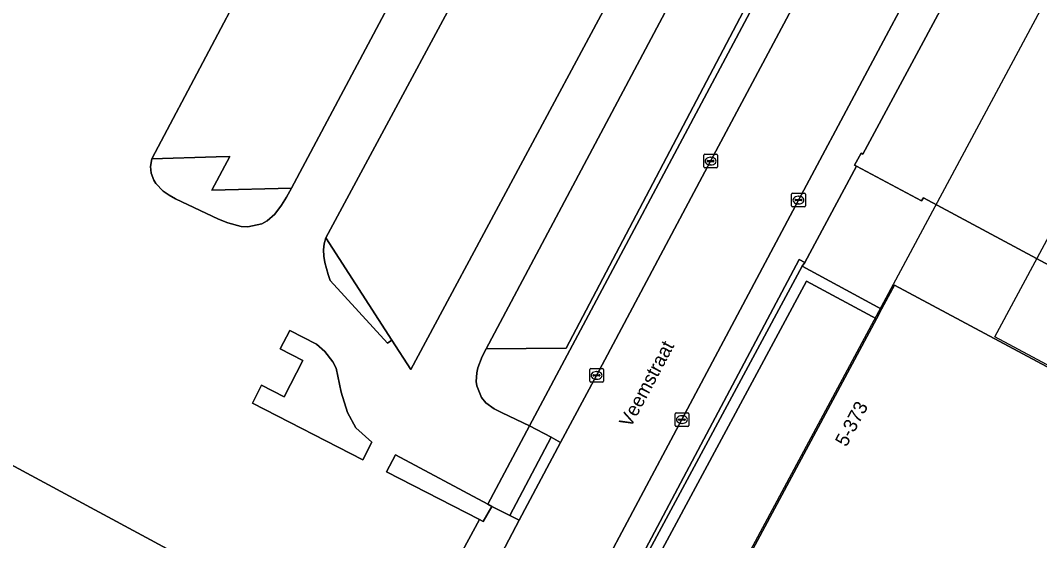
# Model space of a CAD drawing. Extents: x 159489 to 160304, y 383825 to 384531.
# Drawn here: x 159655.5 to 159729.7, y 384337.5 to 384375.4 of the extents above; entities that cross this region are included whole.
import ezdxf

# ---------------------------------------------------------------- set-up
doc = ezdxf.new("R2010")
doc.units = 0
for name, color, linetype in [('IMGEO_Groenvoorziening', 7, 'Continuous'), ('IMGEO_Kolk', 7, 'Continuous'), ('IMGEO_Openbare_ruimte_label', 7, 'Continuous'), ('IMGEO_Pand', 7, 'Continuous'), ('IMGEO_Pand_nummerreeks', 7, 'Continuous'), ('IMGEO_Pand_overbouw', 7, 'Continuous'), ('IMGEO_Parkeervlak_gesloten', 7, 'Continuous'), ('IMGEO_Rijbaan_lokaal_gesloten', 7, 'Continuous'), ('IMGEO_Rijbaan_lokaal_open', 7, 'Continuous'), ('IMGEO_Terreindeel_open', 7, 'Continuous'), ('IMGEO_Voetpad_gesloten', 7, 'Continuous'), ('IMGEO_Voetpad_halfverhard', 7, 'Continuous'), ('IMGEO_Voetpad_open', 7, 'Continuous')]:
    doc.layers.add(name, color=color, linetype=linetype)

msp = doc.modelspace()

# ---------------------------------------------------------------- linework, layer by layer
at = {"layer": 'IMGEO_Groenvoorziening'}
msp.add_lwpolyline([(159708.865, 384377.474), (159695.239, 384351.569), (159689.415, 384351.507), (159689.138, 384350.948), (159688.825, 384350.131), (159688.744, 384349.77), (159688.704, 384349.145), (159688.743, 384348.821), (159689.096, 384347.961), (159689.398, 384347.593), (159690.017, 384347.143), (159690.578, 384346.856), (159692.573, 384345.906), (159709.411, 384377.5)], dxfattribs=at)
for points in [[(159665.072, 384365.355), (159664.99, 384364.806), (159665.035, 384364.301), (159665.216, 384363.794), (159665.361, 384363.549), (159665.895, 384363.003), (159666.339, 384362.706), (159666.812, 384362.436), (159669.925, 384360.97), (159670.614, 384360.692), (159671.586, 384360.438), (159672.07, 384360.408), (159673.085, 384360.615), (159673.472, 384360.833), (159674.029, 384361.331), (159674.521, 384361.969), (159674.888, 384362.565), (159675.243, 384363.209), (159669.452, 384363.069), (159670.746, 384365.527), (159669.77, 384365.497)], [(159677.739, 384359.604), (159677.632, 384359.163), (159677.584, 384358.715), (159677.604, 384358.26), (159677.677, 384357.808), (159677.785, 384357.366), (159677.918, 384356.933), (159678.065, 384356.505), (159682.228, 384351.922), (159682.548, 384352.155)], [(159681.092, 384344.714), (159679.938, 384345.765), (159679.326, 384346.873), (159678.873, 384348.357), (159678.491, 384350.108), (159678.254, 384350.572), (159677.687, 384351.314), (159677.066, 384351.845), (159675.114, 384352.847), (159674.425, 384351.505), (159676.079, 384350.656), (159674.725, 384348.019), (159673.071, 384348.868), (159672.403, 384347.567), (159680.439, 384343.442)], [(159688.942, 384339.078), (159689.212, 384338.929), (159689.84, 384340.04), (159689.536, 384340.195), (159682.809, 384343.795), (159682.171, 384342.553)]]:
    msp.add_lwpolyline(points, close=True, dxfattribs=at)
at = {"layer": 'IMGEO_Kolk'}
for p, q in [((159705.266, 384364.765), (159705.266, 384365.617)), ((159705.341, 384365.691), (159706.193, 384365.691)), ((159706.267, 384365.617), (159706.267, 384364.765)), ((159705.525, 384365.185), (159705.525, 384365.197)), ((159705.963, 384365.148), (159705.565, 384365.148)), ((159705.568, 384365.234), (159705.966, 384365.234)), ((159705.777, 384364.911), (159705.752, 384364.911)), ((159705.754, 384365.471), (159705.779, 384365.471)), ((159706.009, 384365.197), (159706.009, 384365.185)), ((159706.193, 384364.691), (159705.341, 384364.691)), ((159711.667, 384361.925), (159711.667, 384362.777)), ((159711.742, 384362.851), (159712.594, 384362.851)), ((159712.155, 384362.631), (159712.18, 384362.631)), ((159712.668, 384362.777), (159712.668, 384361.925)), ((159712.594, 384361.851), (159711.742, 384361.851)), ((159711.926, 384362.345), (159711.926, 384362.357)), ((159712.364, 384362.308), (159711.966, 384362.308)), ((159711.969, 384362.394), (159712.367, 384362.394)), ((159712.178, 384362.071), (159712.153, 384362.071)), ((159712.41, 384362.357), (159712.41, 384362.345)), ((159696.963, 384349.157), (159696.963, 384350.009)), ((159697.038, 384350.083), (159697.89, 384350.083)), ((159697.964, 384350.009), (159697.964, 384349.157)), ((159697.222, 384349.577), (159697.222, 384349.589)), ((159697.66, 384349.54), (159697.262, 384349.54)), ((159697.265, 384349.626), (159697.663, 384349.626)), ((159697.474, 384349.303), (159697.449, 384349.303)), ((159697.451, 384349.863), (159697.476, 384349.863)), ((159697.706, 384349.589), (159697.706, 384349.577)), ((159697.89, 384349.083), (159697.038, 384349.083)), ((159703.181, 384345.935), (159703.181, 384346.787)), ((159703.256, 384346.861), (159704.108, 384346.861)), ((159703.44, 384346.355), (159703.44, 384346.367)), ((159703.878, 384346.318), (159703.48, 384346.318)), ((159703.483, 384346.404), (159703.881, 384346.404)), ((159703.669, 384346.641), (159703.694, 384346.641)), ((159703.924, 384346.367), (159703.924, 384346.355)), ((159704.182, 384346.787), (159704.182, 384345.935)), ((159704.108, 384345.861), (159703.256, 384345.861)), ((159703.692, 384346.081), (159703.667, 384346.081))]:
    msp.add_line(p, q, dxfattribs=at)
for points in [[(159705.266, 384364.765), (159705.266, 384365.617)], [(159705.341, 384365.691), (159706.193, 384365.691)], [(159706.267, 384365.617), (159706.267, 384364.765)], [(159706.193, 384364.691), (159705.341, 384364.691)], [(159711.667, 384361.925), (159711.667, 384362.777)], [(159711.742, 384362.851), (159712.594, 384362.851)], [(159712.668, 384362.777), (159712.668, 384361.925)], [(159712.594, 384361.851), (159711.742, 384361.851)], [(159696.963, 384349.157), (159696.963, 384350.009)], [(159697.038, 384350.083), (159697.89, 384350.083)], [(159697.964, 384350.009), (159697.964, 384349.157)], [(159697.89, 384349.083), (159697.038, 384349.083)], [(159703.181, 384345.935), (159703.181, 384346.787)], [(159703.256, 384346.861), (159704.108, 384346.861)], [(159704.182, 384346.787), (159704.182, 384345.935)], [(159704.108, 384345.861), (159703.256, 384345.861)]]:
    msp.add_lwpolyline(points, dxfattribs=at)
for centre, radius, start, end in [((159705.343, 384365.615), 0.0765, 91.55205, 178.44795), ((159705.343, 384365.615), 0.0765, 91.55205, 178.44795), ((159706.191, 384365.615), 0.0765, 1.55205, 88.44795), ((159706.191, 384365.615), 0.0765, 1.55205, 88.44795), ((159705.343, 384364.767), 0.0765, 181.55205, 268.44795), ((159705.343, 384364.767), 0.0765, 181.55205, 268.44795), ((159705.565, 384365.194), 0.0403, 85.87752, 175.75265), ((159705.562, 384365.184), 0.0366, 178.93798, 274.71019), ((159705.966, 384365.191), 0.043, 264.86636, 352.45326), ((159705.97, 384365.196), 0.0386, 1.73085, 96.63898), ((159706.191, 384364.767), 0.0765, 271.55205, 358.44795), ((159706.191, 384364.767), 0.0765, 271.55205, 358.44795), ((159711.744, 384362.775), 0.0765, 91.55205, 178.44795), ((159711.744, 384362.775), 0.0765, 91.55205, 178.44795), ((159712.592, 384362.775), 0.0765, 1.55205, 88.44795), ((159712.592, 384362.775), 0.0765, 1.55205, 88.44795), ((159711.744, 384361.927), 0.0765, 181.55205, 268.44795), ((159711.744, 384361.927), 0.0765, 181.55205, 268.44795), ((159711.966, 384362.354), 0.0403, 85.87752, 175.75265), ((159711.963, 384362.344), 0.0366, 178.93798, 274.71019), ((159712.367, 384362.351), 0.043, 264.86636, 352.45326), ((159712.371, 384362.356), 0.0386, 1.73085, 96.63898), ((159712.592, 384361.927), 0.0765, 271.55205, 358.44795), ((159712.592, 384361.927), 0.0765, 271.55205, 358.44795), ((159697.04, 384350.007), 0.0765, 91.55205, 178.44795), ((159697.04, 384350.007), 0.0765, 91.55205, 178.44795), ((159697.888, 384350.007), 0.0765, 1.55205, 88.44795), ((159697.888, 384350.007), 0.0765, 1.55205, 88.44795), ((159697.262, 384349.586), 0.0403, 85.87752, 175.75265), ((159697.259, 384349.576), 0.0366, 178.93798, 274.71019), ((159697.663, 384349.583), 0.043, 264.86636, 352.45326), ((159697.667, 384349.588), 0.0386, 1.73085, 96.63898), ((159697.04, 384349.159), 0.0765, 181.55205, 268.44795), ((159697.04, 384349.159), 0.0765, 181.55205, 268.44795), ((159697.888, 384349.159), 0.0765, 271.55205, 358.44795), ((159697.888, 384349.159), 0.0765, 271.55205, 358.44795), ((159703.258, 384346.785), 0.0765, 91.55205, 178.44795), ((159703.258, 384346.785), 0.0765, 91.55205, 178.44795), ((159703.48, 384346.364), 0.0403, 85.87752, 175.75265), ((159703.477, 384346.354), 0.0366, 178.93798, 274.71019), ((159703.881, 384346.361), 0.043, 264.86636, 352.45326), ((159703.885, 384346.366), 0.0386, 1.73085, 96.63898), ((159704.106, 384346.785), 0.0765, 1.55205, 88.44795), ((159704.106, 384346.785), 0.0765, 1.55205, 88.44795), ((159703.258, 384345.937), 0.0765, 181.55205, 268.44795), ((159703.258, 384345.937), 0.0765, 181.55205, 268.44795), ((159704.106, 384345.937), 0.0765, 271.55205, 358.44795), ((159704.106, 384345.937), 0.0765, 271.55205, 358.44795)]:
    msp.add_arc(centre, radius, start, end, dxfattribs=at)
for centre, major_axis, ratio, start_param, end_param in [((159705.753, 384365.191), (-0.387, 0.002), 0.722429, 4.712389, 7.853982), ((159705.778, 384365.191), (-0.39, 0.002), 0.717154, 1.570796, 4.712389), ((159712.154, 384362.351), (-0.387, 0.002), 0.722429, 4.712389, 7.853982), ((159712.179, 384362.351), (-0.39, 0.002), 0.717154, 1.570796, 4.712389), ((159697.45, 384349.583), (-0.387, 0.002), 0.722429, 4.712389, 7.853982), ((159697.475, 384349.583), (-0.39, 0.002), 0.717154, 1.570796, 4.712389), ((159703.668, 384346.361), (-0.387, 0.002), 0.722429, 4.712389, 7.853982), ((159703.693, 384346.361), (-0.39, 0.002), 0.717154, 1.570796, 4.712389)]:
    msp.add_ellipse(centre, major_axis=major_axis, ratio=ratio, start_param=start_param, end_param=end_param, dxfattribs=at)
at = {"layer": 'IMGEO_Pand'}
for points in [[(159783.397, 384375.103), (159766.339, 384384.271), (159766.74, 384385.035), (159762.446, 384387.363), (159762.034, 384386.593), (159757.242, 384389.159), (159757.112, 384388.916), (159743.621, 384396.119), (159743.741, 384396.343), (159735.557, 384400.786), (159735.425, 384400.573), (159735.575, 384400.48), (159735.43, 384400.212), (159716.859, 384365.689), (159716.722, 384365.762), (159716.246, 384364.892), (159716.4, 384364.81), (159721.137, 384362.285), (159721.26, 384362.516), (159807.547, 384316.187)], [(159654.35, 384302.429), (159658.906, 384300.083), (159659.615, 384299.615), (159661.561, 384298.656), (159662.117, 384298.273), (159662.86, 384299.656), (159664.884, 384298.565), (159664.142, 384297.181), (159665.865, 384296.34), (159667.893, 384300.102), (159668.458, 384301.152), (159672.803, 384309.214), (159678.599, 384319.969), (159679.567, 384321.765), (159682.896, 384327.942), (159623.816, 384359.804)]]:
    msp.add_lwpolyline(points, dxfattribs=at)
msp.add_lwpolyline([(159744.495, 384340.27), (159745.463, 384342.08), (159719.159, 384356.157), (159718.221, 384354.406), (159717.843, 384353.7), (159708.49, 384336.235), (159734.794, 384322.143), (159744.117, 384339.565)], close=True, dxfattribs=at)
at = {"layer": 'IMGEO_Pand_overbouw'}
for points in [[(159772.845, 384392.873), (159746.364, 384407.132), (159719.057, 384356.211), (159708.316, 384336.181), (159708.428, 384336.121), (159728.589, 384325.319), (159734.596, 384322.101), (159734.859, 384321.96), (159745.598, 384342.008)], [(159738.212, 384346.096), (159726.464, 384352.384), (159749.757, 384395.713), (159761.464, 384389.436)], [(159745.463, 384342.08), (159744.495, 384340.27), (159744.117, 384339.565), (159734.794, 384322.143), (159708.49, 384336.235), (159717.843, 384353.7), (159718.221, 384354.406), (159719.159, 384356.157)]]:
    msp.add_lwpolyline(points, close=True, dxfattribs=at)
at = {"layer": 'IMGEO_Parkeervlak_gesloten'}
for points in [[(159687.417, 384386.081), (159678.896, 384385.666), (159678.738, 384385.659), (159675.733, 384385.513), (159665.311, 384365.821), (159665.072, 384365.355), (159669.77, 384365.497), (159670.746, 384365.527), (159669.452, 384363.069), (159675.243, 384363.209)], [(159698.84, 384377.821), (159695.932, 384382.421), (159695.678, 384382.553), (159694.411, 384380.114), (159691.369, 384384.932), (159677.739, 384359.604), (159682.548, 384352.155), (159683.929, 384350.016)], [(159708.865, 384377.474), (159703.07, 384377.2), (159689.415, 384351.507), (159695.239, 384351.569)]]:
    msp.add_lwpolyline(points, close=True, dxfattribs=at)
at = {"layer": 'IMGEO_Rijbaan_lokaal_gesloten'}
for points in [[(159692.548, 384325.527), (159695.619, 384331.21), (159697.323, 384334.416), (159703.682, 384346.361), (159712.168, 384362.351), (159726.086, 384388.453), (159715.08, 384394.302), (159699.103, 384402.825), (159698.719, 384403.028)], [(159715.18, 384382.91), (159714.933, 384382.439), (159714.712, 384381.993), (159711.677, 384376.272), (159705.767, 384365.191), (159697.464, 384349.583), (159694.841, 384344.687), (159691.838, 384339.042), (159690.043, 384335.667), (159689.333, 384334.311), (159686.251, 384328.615), (159679.789, 384316.65), (159671.493, 384301.187), (159668.202, 384295.09), (159666.594, 384292.109)]]:
    msp.add_lwpolyline(points, dxfattribs=at)
at = {"layer": 'IMGEO_Rijbaan_lokaal_open'}
for points in [[(159687.417, 384386.081), (159675.243, 384363.209), (159674.888, 384362.565), (159674.521, 384361.969), (159674.029, 384361.331), (159673.472, 384360.833), (159673.085, 384360.615), (159672.07, 384360.408), (159671.586, 384360.438), (159670.614, 384360.692), (159669.925, 384360.97), (159666.812, 384362.436), (159666.339, 384362.706), (159665.895, 384363.003), (159665.361, 384363.549), (159665.216, 384363.794), (159665.035, 384364.301), (159664.99, 384364.806), (159665.072, 384365.355), (159665.311, 384365.821), (159675.733, 384385.513)], [(159623.816, 384359.804), (159682.896, 384327.942), (159688.942, 384339.078), (159682.171, 384342.553), (159682.809, 384343.795), (159689.536, 384340.195), (159692.573, 384345.906), (159690.578, 384346.856), (159690.017, 384347.143), (159689.398, 384347.593), (159689.096, 384347.961), (159688.743, 384348.821), (159688.704, 384349.145), (159688.744, 384349.77), (159688.825, 384350.131), (159689.138, 384350.948), (159689.415, 384351.507), (159703.07, 384377.2)]]:
    msp.add_lwpolyline(points, dxfattribs=at)
for points in [[(159691.369, 384384.932), (159695.678, 384382.553), (159695.932, 384382.421), (159698.08, 384381.33), (159698.461, 384381.082), (159698.767, 384380.821), (159699.117, 384380.297), (159699.236, 384380.001), (159699.314, 384379.655), (159699.302, 384379.126), (159699.195, 384378.691), (159699.032, 384378.256), (159698.84, 384377.821), (159683.929, 384350.016), (159682.548, 384352.155), (159682.228, 384351.922), (159678.065, 384356.505), (159677.918, 384356.933), (159677.785, 384357.366), (159677.677, 384357.808), (159677.604, 384358.26), (159677.584, 384358.715), (159677.632, 384359.163), (159677.739, 384359.604)], [(159681.092, 384344.714), (159680.439, 384343.442), (159672.403, 384347.567), (159673.071, 384348.868), (159674.725, 384348.019), (159676.079, 384350.656), (159674.425, 384351.505), (159675.114, 384352.847), (159677.066, 384351.845), (159677.687, 384351.314), (159678.254, 384350.572), (159678.491, 384350.108), (159678.873, 384348.357), (159679.326, 384346.873), (159679.938, 384345.765)]]:
    msp.add_lwpolyline(points, close=True, dxfattribs=at)
at = {"layer": 'IMGEO_Terreindeel_open'}
msp.add_lwpolyline([(159797.007, 384309.896), (159741.046, 384317.91), (159726.866, 384319.977), (159700.707, 384334.064), (159712.762, 384356.443), (159717.843, 384353.7), (159718.221, 384354.406), (159712.442, 384357.532), (159699.61, 384333.72), (159726.44, 384319.286), (159726.801, 384319.234), (159741.002, 384317.183), (159741.576, 384317.086), (159796.909, 384309.117), (159800.043, 384308.652), (159800.185, 384309.411), (159801.736, 384308.601), (159802.101, 384309.308), (159781.459, 384320.418), (159744.495, 384340.27), (159744.117, 384339.565), (159781.262, 384319.609), (159800.092, 384309.462)], close=True, dxfattribs=at)
at = {"layer": 'IMGEO_Voetpad_gesloten'}
msp.add_lwpolyline([(159744.117, 384339.565), (159734.794, 384322.143), (159708.49, 384336.235), (159717.843, 384353.7), (159712.762, 384356.443), (159700.707, 384334.064), (159726.866, 384319.977), (159741.046, 384317.91), (159797.007, 384309.896), (159800.092, 384309.462), (159781.262, 384319.609)], close=True, dxfattribs=at)
at = {"layer": 'IMGEO_Voetpad_halfverhard'}
msp.add_lwpolyline([(159807.288, 384315.703), (159807.547, 384316.187), (159721.26, 384362.516), (159721.137, 384362.285), (159716.4, 384364.81), (159712.638, 384357.799), (159712.442, 384357.532), (159718.221, 384354.406), (159719.159, 384356.157), (159745.463, 384342.08), (159744.495, 384340.27), (159781.459, 384320.418), (159802.101, 384309.308), (159803.465, 384308.568)], close=True, dxfattribs=at)
at = {"layer": 'IMGEO_Voetpad_open'}
for points in [[(159716.4, 384364.81), (159716.246, 384364.892), (159716.722, 384365.762), (159716.859, 384365.689), (159735.43, 384400.212), (159734.206, 384400.857), (159733.716, 384401.115), (159727.917, 384390.329), (159724.822, 384391.986), (159699.746, 384405.407), (159698.699, 384406.62), (159698.393, 384408.204), (159698.776, 384409.754), (159700.205, 384411.574), (159701.316, 384412.99), (159701.045, 384413.801), (159700.919, 384414.179), (159699.604, 384413.761)], [(159698.719, 384403.028), (159699.103, 384402.825), (159715.08, 384394.302), (159726.086, 384388.453), (159712.168, 384362.351), (159703.682, 384346.361), (159697.323, 384334.416), (159699.16, 384333.403), (159712.207, 384358.023), (159712.638, 384357.799), (159716.4, 384364.81)]]:
    msp.add_lwpolyline(points, dxfattribs=at)
for points in [[(159711.677, 384376.272), (159710.944, 384376.661), (159709.411, 384377.5), (159692.573, 384345.906), (159694.163, 384345.083), (159694.841, 384344.687), (159697.464, 384349.583), (159705.767, 384365.191)], [(159712.442, 384357.532), (159712.638, 384357.799), (159712.207, 384358.023), (159699.16, 384333.403), (159699.381, 384333.281), (159726.485, 384318.691), (159726.801, 384319.234), (159726.44, 384319.286), (159699.61, 384333.72)], [(159694.163, 384345.083), (159692.573, 384345.906), (159689.536, 384340.195), (159689.84, 384340.04), (159691.141, 384339.376)], [(159694.841, 384344.687), (159694.163, 384345.083), (159691.141, 384339.376), (159691.838, 384339.042)], [(159686.251, 384328.615), (159685.521, 384329.001), (159688.615, 384334.703), (159689.333, 384334.311), (159690.043, 384335.667), (159691.838, 384339.042), (159691.141, 384339.376), (159689.84, 384340.04), (159689.212, 384338.929), (159688.942, 384339.078), (159682.896, 384327.942), (159679.567, 384321.765), (159678.599, 384319.969), (159672.803, 384309.214), (159668.458, 384301.152), (159667.893, 384300.102), (159665.865, 384296.34), (159668.202, 384295.09), (159671.493, 384301.187), (159679.789, 384316.65)]]:
    msp.add_lwpolyline(points, close=True, dxfattribs=at)

# ---------------------------------------------------------------- texts
at = {"layer": 'IMGEO_Openbare_ruimte_label'}
msp.add_text('Veemstraat', height=1, rotation=62.02527, dxfattribs=at).set_placement((159699.942, 384345.717))
at = {"layer": 'IMGEO_Pand_nummerreeks'}
msp.add_text('5-373', height=1, rotation=61.82788, dxfattribs=at).set_placement((159715.658, 384344.324))

doc.saveas('drawing.dxf')
